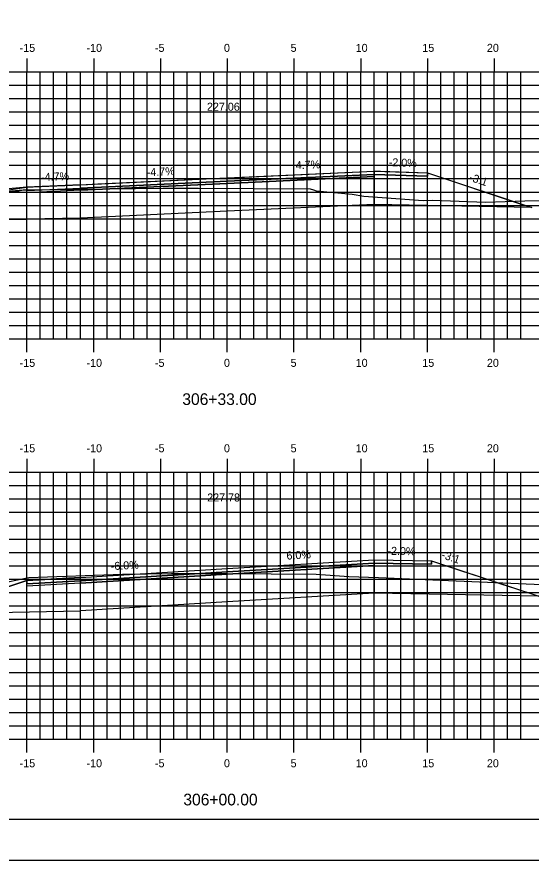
# Model space of a CAD drawing. Extents: x 1137433 to 1137603, y 608981 to 609091.
# Drawn here: x 1137499.9 to 1137538.4, y 608981.3 to 609044.5 of the extents above; entities that cross this region are included whole.
import ezdxf

# ---------------------------------------------------------------- set-up
doc = ezdxf.new("R2010")
doc.units = 0
for name, color, linetype in [('ANNOTATION', 7, 'Continuous'), ('BORDER', 7, 'Continuous'), ('D_Roadway_Centerline', 7, 'Continuous'), ('D_Roadway_Centerline_Text', 7, 'Continuous'), ('D_Roadway_Edge_Shoulder', 7, 'Continuous'), ('D_Roadway_Edge_TW', 7, 'Continuous'), ('D_Roadway_Pavement', 7, 'Continuous'), ('D_Roadway_SubGrade', 7, 'Continuous'), ('H_V ANNOTATION', 7, 'Continuous'), ('MAJOR', 7, 'Continuous'), ('MINOR', 7, 'Continuous'), ('PLOT BOUNDARY', 7, 'Continuous'), ('S_Roadway_Centerline', 7, 'Continuous')]:
    doc.layers.add(name, color=color, linetype=linetype)

msp = doc.modelspace()

# ---------------------------------------------------------------- linework, layer by layer
for points in [[(1137480.733, 609028.805), (1137483.056, 609029.142), (1137500.653, 609031.693), (1137501.13, 609031.716), (1137504.653, 609031.88), (1137505.953, 609031.941), (1137515.653, 609032.393), (1137516.953, 609032.453), (1137526.653, 609032.905), (1137527.13, 609032.89), (1137530.653, 609032.772), (1137537.514, 609030.485), (1137538.461, 609030.169)], [(1137483.968, 609000.475), (1137485.218, 609000.445), (1137486.468, 609000.245), (1137487.718, 608999.875), (1137488.968, 608999.335), (1137490.184, 608998.727), (1137493.184, 608999.727), (1137500.652, 609002.217), (1137500.653, 609002.217), (1137504.653, 609002.457), (1137515.653, 609003.117), (1137526.653, 609003.777), (1137530.966, 609003.69), (1137533.053, 609003.002), (1137534.745, 609002.444), (1137536.143, 609001.984), (1137537.258, 609001.616), (1137538.984, 609001.048)]]:
    msp.add_lwpolyline(points)
at = {"layer": 'BORDER'}
msp.add_lwpolyline([(1137440.653, 608984.335), (1137600.653, 608984.335), (1137600.653, 609089.335), (1137440.653, 609089.335)], close=True, dxfattribs=at)
at = {"layer": 'D_Roadway_Edge_Shoulder'}
for points in [[(1137526.653, 609032.905), (1137530.653, 609032.772), (1137530.653, 609032.522), (1137526.653, 609032.655)], [(1137504.653, 609031.88), (1137500.653, 609031.693), (1137500.653, 609031.443), (1137504.653, 609031.63)], [(1137526.653, 609003.777), (1137530.966, 609003.69), (1137530.966, 609003.44), (1137526.653, 609003.527)], [(1137504.653, 609002.457), (1137500.653, 609002.217), (1137500.653, 609001.967), (1137504.653, 609002.207)]]:
    msp.add_lwpolyline(points, close=True, dxfattribs=at)
msp.add_lwpolyline([(1137473.862, 609028.455), (1137483.653, 609029.337), (1137494.653, 609030.987), (1137500.653, 609031.527)], dxfattribs=at)
at = {"layer": 'D_Roadway_Edge_TW'}
for points in [[(1137504.653, 609031.63), (1137504.653, 609031.88), (1137515.653, 609032.393), (1137526.653, 609032.905), (1137526.653, 609032.655), (1137515.653, 609032.143)], [(1137504.653, 609031.463), (1137500.65, 609031.276), (1137500.653, 609031.443), (1137504.653, 609031.63)], [(1137504.653, 609002.207), (1137504.653, 609002.457), (1137515.653, 609003.117), (1137526.653, 609003.777), (1137526.653, 609003.527), (1137515.653, 609002.867)], [(1137504.653, 609002.04), (1137500.653, 609001.8), (1137500.653, 609001.967), (1137504.653, 609002.207)]]:
    msp.add_lwpolyline(points, close=True, dxfattribs=at)
at = {"layer": 'D_Roadway_Pavement'}
for points in [[(1137504.653, 609031.463), (1137504.653, 609031.63), (1137515.653, 609032.143), (1137526.653, 609032.655), (1137526.653, 609032.489), (1137515.653, 609031.976)], [(1137504.653, 609002.04), (1137504.653, 609002.207), (1137515.653, 609002.867), (1137526.653, 609003.527), (1137526.653, 609003.36), (1137515.653, 609002.7)]]:
    msp.add_lwpolyline(points, close=True, dxfattribs=at)
at = {"layer": 'D_Roadway_SubGrade'}
for p, q in [((1137500.653, 609031.693), (1137494.653, 609031.153)), ((1137488.653, 609029.141), (1137500.653, 609029.3)), ((1137488.653, 609029.141), (1137500.653, 609029.3)), ((1137504.653, 609029.38), (1137500.653, 609029.3))]:
    msp.add_line(p, q, dxfattribs=at)
for points in [[(1137504.653, 609029.38), (1137504.653, 609031.463), (1137515.653, 609031.976), (1137526.653, 609032.489), (1137526.653, 609030.405), (1137515.653, 609029.893)], [(1137526.653, 609032.489), (1137526.653, 609032.655), (1137530.653, 609032.522), (1137530.653, 609032.772), (1137530.653, 609032.772), (1137538.461, 609030.169), (1137526.653, 609030.405)], [(1137504.653, 608999.957), (1137504.653, 609002.04), (1137515.653, 609002.7), (1137526.653, 609003.36), (1137526.653, 609001.277), (1137515.653, 609000.617)], [(1137526.653, 609003.36), (1137526.653, 609003.527), (1137530.966, 609003.44), (1137530.966, 609003.69), (1137530.966, 609003.69), (1137538.984, 609001.048), (1137526.653, 609001.277)], [(1137504.653, 609002.04), (1137504.653, 609002.207), (1137500.653, 609001.967), (1137500.653, 609002.217), (1137500.652, 609002.217), (1137493.184, 608999.727), (1137504.653, 608999.957)]]:
    msp.add_lwpolyline(points, close=True, dxfattribs=at)
at = {"layer": 'MAJOR'}
for p, q in [((1137500.653, 609041.337), (1137500.653, 609040.335)), ((1137505.653, 609041.337), (1137505.653, 609040.335)), ((1137510.653, 609041.337), (1137510.653, 609040.335)), ((1137515.653, 609041.337), (1137515.653, 609040.335)), ((1137520.653, 609041.337), (1137520.653, 609040.335)), ((1137525.653, 609041.337), (1137525.653, 609040.335)), ((1137530.653, 609041.337), (1137530.653, 609040.335)), ((1137535.653, 609041.337), (1137535.653, 609040.335)), ((1137445.653, 609040.335), (1137585.653, 609040.335)), ((1137445.653, 609040.335), (1137585.653, 609040.335)), ((1137500.653, 609020.335), (1137500.653, 609040.335)), ((1137505.653, 609020.335), (1137505.653, 609040.335)), ((1137510.653, 609020.335), (1137510.653, 609040.335)), ((1137515.653, 609020.335), (1137515.653, 609040.335)), ((1137520.653, 609020.335), (1137520.653, 609040.335)), ((1137525.653, 609020.335), (1137525.653, 609040.335)), ((1137530.653, 609020.335), (1137530.653, 609040.335)), ((1137535.653, 609020.335), (1137535.653, 609040.335)), ((1137445.653, 609035.335), (1137585.653, 609035.335)), ((1137445.653, 609030.335), (1137585.653, 609030.335)), ((1137445.653, 609025.335), (1137585.653, 609025.335)), ((1137445.653, 609020.335), (1137585.653, 609020.335)), ((1137445.653, 609020.335), (1137585.653, 609020.335)), ((1137500.653, 609019.333), (1137500.653, 609020.335)), ((1137505.653, 609019.333), (1137505.653, 609020.335)), ((1137510.653, 609019.333), (1137510.653, 609020.335)), ((1137515.653, 609019.333), (1137515.653, 609020.335)), ((1137520.653, 609019.333), (1137520.653, 609020.335)), ((1137525.653, 609019.333), (1137525.653, 609020.335)), ((1137530.653, 609019.333), (1137530.653, 609020.335)), ((1137535.653, 609019.333), (1137535.653, 609020.335)), ((1137500.653, 609011.337), (1137500.653, 609010.335)), ((1137505.653, 609011.337), (1137505.653, 609010.335)), ((1137510.653, 609011.337), (1137510.653, 609010.335)), ((1137515.653, 609011.337), (1137515.653, 609010.335)), ((1137520.653, 609011.337), (1137520.653, 609010.335)), ((1137525.653, 609011.337), (1137525.653, 609010.335)), ((1137530.653, 609011.337), (1137530.653, 609010.335)), ((1137535.653, 609011.337), (1137535.653, 609010.335)), ((1137445.653, 609010.335), (1137585.653, 609010.335)), ((1137445.653, 609010.335), (1137585.653, 609010.335)), ((1137500.653, 608990.335), (1137500.653, 609010.335)), ((1137505.653, 608990.335), (1137505.653, 609010.335)), ((1137510.653, 608990.335), (1137510.653, 609010.335)), ((1137515.653, 608990.335), (1137515.653, 609010.335)), ((1137520.653, 608990.335), (1137520.653, 609010.335)), ((1137525.653, 608990.335), (1137525.653, 609010.335)), ((1137530.653, 608990.335), (1137530.653, 609010.335)), ((1137535.653, 608990.335), (1137535.653, 609010.335)), ((1137445.653, 609005.335), (1137585.653, 609005.335)), ((1137445.653, 609000.335), (1137585.653, 609000.335)), ((1137445.653, 608995.335), (1137585.653, 608995.335)), ((1137445.653, 608990.335), (1137585.653, 608990.335)), ((1137445.653, 608990.335), (1137585.653, 608990.335)), ((1137500.653, 608989.333), (1137500.653, 608990.335)), ((1137505.653, 608989.333), (1137505.653, 608990.335)), ((1137510.653, 608989.333), (1137510.653, 608990.335)), ((1137515.653, 608989.333), (1137515.653, 608990.335)), ((1137520.653, 608989.333), (1137520.653, 608990.335)), ((1137525.653, 608989.333), (1137525.653, 608990.335)), ((1137530.653, 608989.333), (1137530.653, 608990.335)), ((1137535.653, 608989.333), (1137535.653, 608990.335))]:
    msp.add_line(p, q, dxfattribs=at)
at = {"layer": 'MINOR'}
for p, q in [((1137501.653, 609020.335), (1137501.653, 609040.335)), ((1137502.653, 609020.335), (1137502.653, 609040.335)), ((1137503.653, 609020.335), (1137503.653, 609040.335)), ((1137504.653, 609020.335), (1137504.653, 609040.335)), ((1137506.653, 609020.335), (1137506.653, 609040.335)), ((1137507.653, 609020.335), (1137507.653, 609040.335)), ((1137508.653, 609020.335), (1137508.653, 609040.335)), ((1137509.653, 609020.335), (1137509.653, 609040.335)), ((1137511.653, 609020.335), (1137511.653, 609040.335)), ((1137512.653, 609020.335), (1137512.653, 609040.335)), ((1137513.653, 609020.335), (1137513.653, 609040.335)), ((1137514.653, 609020.335), (1137514.653, 609040.335)), ((1137516.653, 609020.335), (1137516.653, 609040.335)), ((1137517.653, 609020.335), (1137517.653, 609040.335)), ((1137518.653, 609020.335), (1137518.653, 609040.335)), ((1137519.653, 609020.335), (1137519.653, 609040.335)), ((1137521.653, 609020.335), (1137521.653, 609040.335)), ((1137522.653, 609020.335), (1137522.653, 609040.335)), ((1137523.653, 609020.335), (1137523.653, 609040.335)), ((1137524.653, 609020.335), (1137524.653, 609040.335)), ((1137526.653, 609020.335), (1137526.653, 609040.335)), ((1137527.653, 609020.335), (1137527.653, 609040.335)), ((1137528.653, 609020.335), (1137528.653, 609040.335)), ((1137529.653, 609020.335), (1137529.653, 609040.335)), ((1137531.653, 609020.335), (1137531.653, 609040.335)), ((1137532.653, 609020.335), (1137532.653, 609040.335)), ((1137533.653, 609020.335), (1137533.653, 609040.335)), ((1137534.653, 609020.335), (1137534.653, 609040.335)), ((1137536.653, 609020.335), (1137536.653, 609040.335)), ((1137537.653, 609020.335), (1137537.653, 609040.335)), ((1137445.653, 609039.335), (1137585.653, 609039.335)), ((1137445.653, 609038.335), (1137585.653, 609038.335)), ((1137445.653, 609037.335), (1137585.653, 609037.335)), ((1137445.653, 609036.335), (1137585.653, 609036.335)), ((1137445.653, 609034.335), (1137585.653, 609034.335)), ((1137445.653, 609033.335), (1137585.653, 609033.335)), ((1137445.653, 609032.335), (1137585.653, 609032.335)), ((1137445.653, 609031.335), (1137585.653, 609031.335)), ((1137445.653, 609029.335), (1137585.653, 609029.335)), ((1137445.653, 609028.335), (1137585.653, 609028.335)), ((1137445.653, 609027.335), (1137585.653, 609027.335)), ((1137445.653, 609026.335), (1137585.653, 609026.335)), ((1137445.653, 609024.335), (1137585.653, 609024.335)), ((1137445.653, 609023.335), (1137585.653, 609023.335)), ((1137445.653, 609022.335), (1137585.653, 609022.335)), ((1137445.653, 609021.335), (1137585.653, 609021.335)), ((1137501.653, 608990.335), (1137501.653, 609010.335)), ((1137502.653, 608990.335), (1137502.653, 609010.335)), ((1137503.653, 608990.335), (1137503.653, 609010.335)), ((1137504.653, 608990.335), (1137504.653, 609010.335)), ((1137506.653, 608990.335), (1137506.653, 609010.335)), ((1137507.653, 608990.335), (1137507.653, 609010.335)), ((1137508.653, 608990.335), (1137508.653, 609010.335)), ((1137509.653, 608990.335), (1137509.653, 609010.335)), ((1137511.653, 608990.335), (1137511.653, 609010.335)), ((1137512.653, 608990.335), (1137512.653, 609010.335)), ((1137513.653, 608990.335), (1137513.653, 609010.335)), ((1137514.653, 608990.335), (1137514.653, 609010.335)), ((1137516.653, 608990.335), (1137516.653, 609010.335)), ((1137517.653, 608990.335), (1137517.653, 609010.335)), ((1137518.653, 608990.335), (1137518.653, 609010.335)), ((1137519.653, 608990.335), (1137519.653, 609010.335)), ((1137521.653, 608990.335), (1137521.653, 609010.335)), ((1137522.653, 608990.335), (1137522.653, 609010.335)), ((1137523.653, 608990.335), (1137523.653, 609010.335)), ((1137524.653, 608990.335), (1137524.653, 609010.335)), ((1137526.653, 608990.335), (1137526.653, 609010.335)), ((1137527.653, 608990.335), (1137527.653, 609010.335)), ((1137528.653, 608990.335), (1137528.653, 609010.335)), ((1137529.653, 608990.335), (1137529.653, 609010.335)), ((1137531.653, 608990.335), (1137531.653, 609010.335)), ((1137532.653, 608990.335), (1137532.653, 609010.335)), ((1137533.653, 608990.335), (1137533.653, 609010.335)), ((1137534.653, 608990.335), (1137534.653, 609010.335)), ((1137536.653, 608990.335), (1137536.653, 609010.335)), ((1137537.653, 608990.335), (1137537.653, 609010.335)), ((1137445.653, 609009.335), (1137585.653, 609009.335)), ((1137445.653, 609008.335), (1137585.653, 609008.335)), ((1137445.653, 609007.335), (1137585.653, 609007.335)), ((1137445.653, 609006.335), (1137585.653, 609006.335)), ((1137445.653, 609004.335), (1137585.653, 609004.335)), ((1137445.653, 609003.335), (1137585.653, 609003.335)), ((1137445.653, 609002.335), (1137585.653, 609002.335)), ((1137445.653, 609001.335), (1137585.653, 609001.335)), ((1137445.653, 608999.335), (1137585.653, 608999.335)), ((1137445.653, 608998.335), (1137585.653, 608998.335)), ((1137445.653, 608997.335), (1137585.653, 608997.335)), ((1137445.653, 608996.335), (1137585.653, 608996.335)), ((1137445.653, 608994.335), (1137585.653, 608994.335)), ((1137445.653, 608993.335), (1137585.653, 608993.335)), ((1137445.653, 608992.335), (1137585.653, 608992.335)), ((1137445.653, 608991.335), (1137585.653, 608991.335))]:
    msp.add_line(p, q, dxfattribs=at)
at = {"layer": 'PLOT BOUNDARY'}
msp.add_lwpolyline([(1137432.56, 608981.276), (1137602.56, 608981.276), (1137602.56, 609091.276), (1137432.56, 609091.276)], close=True, dxfattribs=at)
at = {"layer": 'S_Roadway_Centerline'}
for points in [[(1137445.653, 609028.703), (1137460.066, 609028.556), (1137460.633, 609028.548), (1137478.111, 609028.646), (1137479.06, 609028.67), (1137486.804, 609028.946), (1137487.264, 609028.966), (1137498.159, 609031.27), (1137499.941, 609031.407), (1137500.381, 609031.497), (1137500.618, 609031.505), (1137510.823, 609031.631), (1137513.506, 609031.615), (1137521.857, 609031.577), (1137522.115, 609031.498), (1137522.315, 609031.418), (1137525.004, 609031.182), (1137525.888, 609031.035), (1137530.343, 609030.697), (1137531.057, 609030.727), (1137534.993, 609030.582), (1137537.95, 609030.665), (1137547.085, 609030.758)], [(1137445.653, 609000.068), (1137449.602, 608999.97), (1137450.522, 608999.958), (1137471.63, 609000.04), (1137476.229, 609000.162), (1137479.292, 609000.271), (1137487.646, 609000.636), (1137491.658, 609000.725), (1137493.508, 609000.954), (1137500.799, 609002.457), (1137507.803, 609002.706), (1137511.492, 609002.758), (1137515.564, 609002.741), (1137522.315, 609002.7), (1137524.764, 609002.536), (1137526.981, 609002.445), (1137539.217, 609001.937)]]:
    msp.add_lwpolyline(points, dxfattribs=at)

# ---------------------------------------------------------------- texts
at = {"layer": 'ANNOTATION'}
for s, rotation, p in [('4.7%', 2.66818, (1137520.8, 609033.034)), ('-2.0%', 358.08717, (1137527.748, 609033.27)), ('-4.7%', 2.66814, (1137501.728, 609032.145)), ('-4.7%', 2.66816, (1137509.639, 609032.513)), ('-3:1', 341.5654, (1137533.733, 609032.199)), ('6.0%', 3.43363, (1137520.11, 609003.786)), ('-2.0%', 358.85424, (1137527.653, 609004.157)), ('-3:1', 341.75001, (1137531.656, 609003.916)), ('-6.0%', 3.43363, (1137506.95, 609002.996))]:
    msp.add_text(s, height=0.6, rotation=rotation, dxfattribs=at).set_placement(p)
at = {"layer": 'D_Roadway_Centerline'}
for s, p in [('C', (1137515.648, 609032.393)), ('L', (1137515.653, 609032.385)), ('C', (1137515.648, 609003.117)), ('L', (1137515.653, 609003.109))]:
    msp.add_text(s, height=0.0146, dxfattribs=at).set_placement(p)
at = {"layer": 'D_Roadway_Centerline_Text'}
for s, p in [('227.06', (1137514.138, 609037.425)), ('227.78', (1137514.157, 609008.149))]:
    msp.add_text(s, height=0.6, dxfattribs=at).set_placement(p)
at = {"layer": 'H_V ANNOTATION'}
for s, height, p in [('-15', 0.6, (1137500.11, 609041.835)), ('-10', 0.6, (1137505.118, 609041.835)), ('-5', 0.6, (1137510.243, 609041.835)), ('0', 0.6, (1137515.412, 609041.835)), ('5', 0.6, (1137520.404, 609041.835)), ('10', 0.6, (1137525.278, 609041.835)), ('15', 0.6, (1137530.27, 609041.835)), ('20', 0.6, (1137535.107, 609041.835)), ('-15', 0.6, (1137500.11, 609018.235)), ('-10', 0.6, (1137505.118, 609018.235)), ('-5', 0.6, (1137510.243, 609018.235)), ('0', 0.6, (1137515.412, 609018.235)), ('5', 0.6, (1137520.404, 609018.235)), ('10', 0.6, (1137525.278, 609018.235)), ('15', 0.6, (1137530.27, 609018.235)), ('20', 0.6, (1137535.107, 609018.235)), ('306+33.00', 0.875, (1137512.29, 609015.378)), ('-15', 0.6, (1137500.11, 609011.835)), ('-10', 0.6, (1137505.118, 609011.835)), ('-5', 0.6, (1137510.243, 609011.835)), ('0', 0.6, (1137515.412, 609011.835)), ('5', 0.6, (1137520.404, 609011.835)), ('10', 0.6, (1137525.278, 609011.835)), ('15', 0.6, (1137530.27, 609011.835)), ('20', 0.6, (1137535.107, 609011.835)), ('-15', 0.6, (1137500.11, 608988.235)), ('-10', 0.6, (1137505.118, 608988.235)), ('-5', 0.6, (1137510.243, 608988.235)), ('0', 0.6, (1137515.412, 608988.235)), ('5', 0.6, (1137520.404, 608988.235)), ('10', 0.6, (1137525.278, 608988.235)), ('15', 0.6, (1137530.27, 608988.235)), ('20', 0.6, (1137535.107, 608988.235)), ('306+00.00', 0.875, (1137512.368, 608985.378))]:
    msp.add_text(s, height=height, dxfattribs=at).set_placement(p)
at = {"layer": 'S_Roadway_Centerline'}
for s, p in [('L', (1137510.815, 609031.623)), ('C', (1137510.818, 609031.631)), ('L', (1137511.484, 609002.751)), ('C', (1137511.487, 609002.758))]:
    msp.add_text(s, height=0.0146, dxfattribs=at).set_placement(p)

doc.saveas('drawing.dxf')
